// Mitsubishi GX Works2 project: MC-34MR-8MTS-F470-FX2N-A例程   PLC: FX2N/FX2NC

PROGRAM MAIN
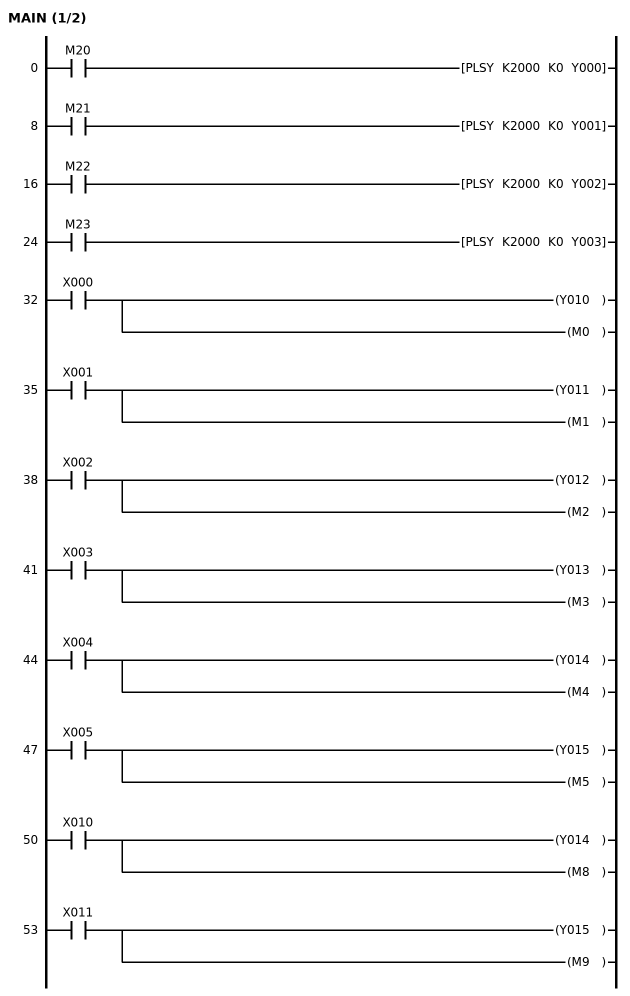
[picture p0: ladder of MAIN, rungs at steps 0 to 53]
0     LD      M20
      PLSY    K2000 K0 Y000
8     LD      M21
      PLSY    K2000 K0 Y001
16    LD      M22
      PLSY    K2000 K0 Y002
24    LD      M23
      PLSY    K2000 K0 Y003
32    LD      X000
      OUT     Y010
      OUT     M0
35    LD      X001
      OUT     Y011
      OUT     M1
38    LD      X002
      OUT     Y012
      OUT     M2
41    LD      X003
      OUT     Y013
      OUT     M3
44    LD      X004
      OUT     Y014
      OUT     M4
47    LD      X005
      OUT     Y015
      OUT     M5
50    LD      X010
      OUT     Y014
      OUT     M8
53    LD      X011
      OUT     Y015
      OUT     M9
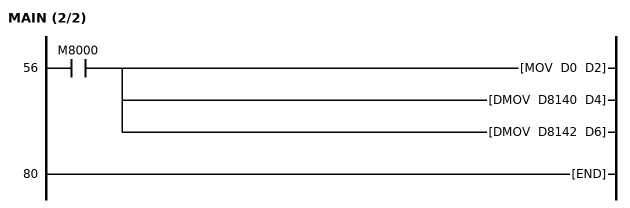
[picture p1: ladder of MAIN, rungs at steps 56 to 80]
56    LD      M8000
      MOV     D0 D2
      DMOV    D8140 D4
      DMOV    D8142 D6
80    END
END_PROGRAM
